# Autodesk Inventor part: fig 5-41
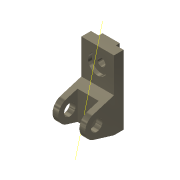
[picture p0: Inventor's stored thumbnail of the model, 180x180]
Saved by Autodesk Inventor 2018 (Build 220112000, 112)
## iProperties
Shininess: 65.0
Angle Display Precision: 2
Document Length Units: 11269
Document Angle Units: 11279
Document Time Units: 11290
Document Mass Units: 11283
Document Length Units Precision: 3
Document Angle Units Precision: 2
Created: 2001-11
Part Number: fig 5-41
Document SubType Name: Modeling
Designer: Renu Muthoo
Density: 1 g/cm^3
Material: Generic
Appearance: Metal-Titanium (Polished)
Density: 0.0
Volumn: 0.0
Area: 0.0
PropertySet Name: Model Information
Control State: 0
Master: False
Checked Out: False
Author: Renu Muthoo
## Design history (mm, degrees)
node "Sketch1"
sketch "Sketch2"
  geometry: L1 (33.257, 104.664)-(33.257, -75.336); L2 (33.257, -75.336)-(8.257, -75.336); L3 (8.257, -75.336)-(-45.451, -59.045); L4 (-45.451, -1.628)-(8.257, 14.664); L5 (8.257, 14.664)-(8.257, 104.664); L6 (8.257, 104.664)-(33.257, 104.664); C1 r 15 at (-36.743, -30.336); A1 r 30 centre (-36.743, -30.336) between (-45.451, -1.628) and (-45.451, -59.045)
  constraints: 12 end point, 2 centre point, 2 equal length, 2 parallel, 2 point on circle, 2 tangent, 1 coincident, 1 perpendicular, 1 vertical
  dimensions: "d0" = 180 distance of L1.start L1.end; "d1" = 30 radius of A1; "d2" = 25 distance of L5.end L1.start; "d3" = 45 distance from line of L2 A1.centre; "d4" = 70 distance from line of L1 A1.centre; "d5" = 30 diameter of C1
extrude "Extrusion1" new body sketch "Sketch2" distance "d6" = 85; taper "d7" = 0 deg
workplane "Work Plane1"
sketch "Sketch3"
  geometry: L1 (15, 62.364)-(70, 62.364); L2 (70, 62.364)-(70, -52.386); L3 (70, -52.386)-(15, -52.386); L4 (15, -52.386)-(15, 62.364); L5 (0, -45)-(0, -28.708) reference
  constraints: 8 end point, 2 parallel, 1 horizontal, 1 perpendicular
  dimensions: "d8" = 55 distance of L1.start L1.end; "d9" = 15 distance between parallel lines of L5 L4
extrude "Extrusion2" cut sketch "Sketch3" distance "d10" = 50; taper "d11" = 0 deg
sketch "Sketch4"
  geometry: L1 (0, 25)-(85, 25) reference; L2 (0, 0)-(0, 25) reference; L3 (20, 25)-(65, 25); L4 (65, 25)-(65, 35); L5 (65, 35)-(20, 35); L6 (20, 35)-(20, 25)
  constraints: 8 end point, 2 parallel, 1 horizontal, 1 perpendicular, 1 point on line
  dimensions: "d12" = 45 distance of L4.end L5.end; "d13" = 10 distance of L3.end L4.end; "d14" = 20 distance between parallel lines of L2 L6
extrude "Extrusion3" join sketch "Sketch4" stored distance "d15" = 50; taper "d16" = 0 deg
sketch "Sketch5"
  geometry: L1 (85, 0)-(85, 90) reference; L2 (0, 90)-(85, 90) reference; 1 further point
  dimensions: "d17" = 42 distance from line of L2 point (42.5, 48); "d18" = 42.5 distance from line of L1 point (42.5, 48)
hole "Hole1" sketch "Sketch5" at (42.5, 48) diameter "d19" = 20; stored, may be unused: countersink angle "d23" = 82 deg, drill point angle "d25" = 118 deg; dims "d20" = 6, "d21" = 50, "d22" = 10, "d24" = 8
workaxis "Work Axis1"
body "Solid1"
